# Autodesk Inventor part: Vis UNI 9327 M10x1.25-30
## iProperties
Shininess: 64.0
Length Units: 11269
Angle Units: 11279
Time Units: 11290
Mass Units: 11283
Length Display Precision: 3
Angle Display Precision: 2
Compacted: True
Part Number: Vis UNI 9327 M10x1.25-30
Document SubType Name: Modeling
Created: 2005-02
Material: Par défaut
Designer: LEGERET Philippe
Catalog Web Link: www.traceparts.com
Description: Vis CHC M10x1.25-30 - 4,8, Grade A - UNI 9327
Density: 0.0
Volumn: 0.0
Area: 0.0
PropertySet Name: Model Information
Control State: 0
Master: False
Checked Out: False
Author: Trace Parts S.A.
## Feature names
1. Base1
